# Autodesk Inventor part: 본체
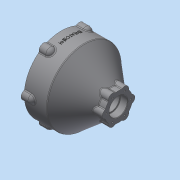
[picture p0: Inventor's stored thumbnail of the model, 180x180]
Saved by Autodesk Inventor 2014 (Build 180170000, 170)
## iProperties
Created: 2026-05
Part Number: 본체
Material: 일반
Document SubType Name: Modeling
Designer: dg
Density: 1 g/cm^3
Appearance: 기본값
Author: dg
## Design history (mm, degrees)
sketch "스케치1"
  geometry: L1 (-63, 0)-(63, 0); L2 (-63, 0)-(-63, 82); L3 (-63, 82)-(-13, 82); L4 (-13, 82)-(48.375, 30.5); L5 (48.375, 30.5)-(63, 30.5); L6 (63, 30.5)-(63, 0); L7 (-63, 73)-(-26, 73); L8 (-26, 73)-(-26, 68); L9 (-26, 68)-(-21, 68); L10 (-21, 68)-(-21, 56); L11 (-21, 56)-(-1, 56); L12 (-1, 56)-(-1, 40); L13 (-1, 40)-(15, 40); L14 (15, 40)-(15, 37); L15 (15, 37)-(19, 37); L16 (19, 37)-(19, 20); L17 (19, 20)-(31, 20); L18 (31, 20)-(31, 17.5); L19 (31, 17.5)-(47, 17.5); L20 (47, 17.5)-(47, 20); L21 (47, 20)-(63, 20); 2 further points
  constraints: 42 end point, 14 parallel, 5 perpendicular, 2 point on line, 1 coincident, 1 horizontal, 1 horizontal alignment, 1 midpoint
  dimensions: "d0" = 126 distance of L1.start L1.end; "d1" = 164 diameter of L3 L1; "d2" = 61 diameter of L5 L1; "d3" = 40 deg angle of L4 L3; "d4" = 50 distance from line of L3.end L2; "d5" = 35 diameter of L19 L1; "d6" = 40 diameter of L21 L1; "d7" = 74 diameter of L15 L1; "d8" = 80 diameter of L13 L1; "d9" = 112 diameter of L11 L1; "d10" = 136 diameter of L9 L1; "d11" = 146 diameter of L7 L1; "d12" = 37 distance of L7.start L7.end; "d13" = 5 distance of L8.end L9.end; "d14" = 25 distance between parallel lines of L12 L8; "d15" = 20 distance between parallel lines of L12 L16; "d16" = 12 distance of L16.end L17.end; "d17" = 16 distance of L20.end L21.end; "d18" = 16 distance of L12.end L13.end
revolve "회전3" stored, may be unused: angle "d36" = 90 deg
sketch "스케치6" dims "d37" = 158
  geometry: C1 r 82 at (0, 0) reference; C2 r 10 at (0, 79); 1 further point
  constraints: 2 vertical alignment, 1 centre point, 1 coincident, 2 other
  dimensions: "d38" = 20 diameter of C2
extrude "돌출4" join sketch "스케치6" distance "d39" = 15; taper "d40" = 0 deg
sketch "스케치7"
  geometry: L1 (-48, 81.424)-(-48, 89) reference; L2 (-48, 82)-(-13, 82) reference; L3 (-59.916, 79)-(-20.021, 79); L4 (-48, 89)-(-48, 69); A1 r 10 centre (-48, 79) between (-48, 69) and (-48, 89); 1 further point
  constraints: 4 end point, 3 point on circle, 2 point on line, 1 centre point, 1 parallel, 1 perpendicular
  dimensions: "d41" = 20 diameter of A1; "d42" = 79 distance from line of point (0, 0) L3
revolve "회전4" sketch "스케치7" stored, may be unused: angle "d43" = 90 deg
sketch "스케치9" dims "d51" = 54
  geometry: C1 r 30.5 at (0, 0) reference; C2 r 9 at (0, -27); 1 further point
  constraints: 2 vertical alignment, 1 centre point, 1 coincident, 2 other
  dimensions: "d52" = 18 diameter of C2
extrude "돌출6" join sketch "스케치9" stored distance "d53" = 0; taper "d54" = 0 deg
revolve "회전5" stored, may be unused: angle "d58" = 90 deg
sketch "스케치10"
  geometry: A1 r 10 centre (-68.416, -118.5) between (-75.366, -111.31) and (-65.664, -128.114) reference; A2 r 10 centre (0, -158) between (-9.702, -160.424) and (9.702, -160.424) reference; A3 r 10 centre (68.416, -118.5) between (65.664, -128.114) and (75.366, -111.31) reference; A4 r 10 centre (68.416, -39.5) between (75.366, -46.69) and (65.664, -29.886) reference; A5 r 10 centre (0, 0) between (9.702, 2.424) and (-9.702, 2.424) reference; A6 r 10 centre (-68.416, -39.5) between (-65.664, -29.886) and (-75.366, -46.69) reference
hole "구멍1" sketch "스케치10" at (0, 0), (68.416, -39.5), (68.416, -118.5), (0, -158), (-68.416, -118.5), (-68.416, -39.5) diameter "d59" = 4.917; stored, may be unused: countersink angle "d63" = 90 deg, drill point angle "d65" = 118 deg; dims "d60" = 12, "d61" = 4, "d62" = 2, "d64" = 14
sketch "스케치11"
  geometry: A1 r 9 centre (0, 0) between (-8.72, -2.227) and (8.72, -2.227) reference
hole "구멍2" sketch "스케치11" at (0, 0) diameter "d66" = 3.242; stored, may be unused: countersink angle "d70" = 90 deg, drill point angle "d72" = 118 deg; dims "d67" = 8, "d68" = 4, "d69" = 2, "d71" = 10
sketch "스케치12" dims "d76" = 124
  geometry: C1 r 68 at (0, 0) reference; C2 r 56 at (0, 0) reference; 2 further points
  constraints: 2 vertical alignment, 1 coincident, 2 other
hole "구멍3" sketch "스케치12" at (0, 62) diameter "d77" = 3.242; stored, may be unused: countersink angle "d81" = 90 deg, drill point angle "d83" = 118 deg; dims "d78" = 8, "d79" = 4, "d80" = 2, "d82" = 10
fillet "모깎기1" dims "d87" = 0.6
fillet "모깎기2" dims "d88" = 1
fillet "모깎기3" dims "d89" = 3
chamfer "모따기1" distance "d90" = 1; stored, may be unused: second distance "d91" = 2, angle "d92" = 45 deg
fillet "모깎기4" dims "d93" = 3
fillet "모깎기5" dims "d94" = 3
fillet "모깎기6" dims "d95" = 3
fillet "모깎기7" dims "d96" = 3
node "작업 평면1"
sketch "스케치13"
  geometry: L1 (-63, -30.625)-(-63, 30.625) reference; 2 further points
  constraints: 1 horizontal alignment, 1 other
  dimensions: "d98" = 20 distance from line of point (-43, 0) L1
feature "엠보싱1" sketch "스케치13" dims "d0" = 126, "d1" = 164, "d2" = 61, "d3" = 40 deg, "d4" = 50, "d5" = 35, "d6" = 40, "d7" = 74, "d8" = 80, "d9" = 112, "d10" = 136, "d11" = 146, "d12" = 37, "d13" = 5, "d14" = 25, "d15" = 20, "d16" = 12, "d17" = 16, "d18" = 16, "d99" = 0.5, "d100" = 0
node "솔리드2"
pattern_circular "원형 패턴1" dims angle "d45" = 360 deg
pattern_circular "원형 패턴2" dims angle "d56" = 360 deg
pattern_circular "원형 패턴3" dims angle "d74" = 360 deg
pattern_circular "원형 패턴4" dims angle "d85" = 360 deg
other parameters: "d97" = 82
